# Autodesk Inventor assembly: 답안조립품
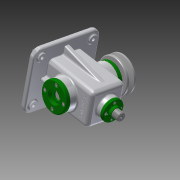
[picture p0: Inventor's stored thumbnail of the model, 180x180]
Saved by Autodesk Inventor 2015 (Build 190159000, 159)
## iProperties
Created: 2016-02
Part Number: 답안조립품
Document SubType Name: Assembly
Designer: Administrator
Author: Administrator
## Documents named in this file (19)
- C:\Users\Administrator\Desktop\답안조립품.iam
- C:\Users\Administrator\Desktop\본체.ipt
- C:\Users\Administrator\Desktop\460219V1005\V-벨트풀리.ipt
- C:\Users\Administrator\Desktop\460219V1005\고정핀.ipt
- C:\Users\Administrator\Desktop\460219V1005\뒤커버.ipt
- C:\Users\Administrator\Desktop\460219V1005\링크.ipt
- C:\Users\Administrator\Desktop\460219V1005\멈춤링 6 x 5.ipt
- C:\Users\Administrator\Desktop\460219V1005\멈춤링 15 x 1.ipt
- C:\Users\Administrator\Desktop\460219V1005\베어링 15 x 35 x 11.ipt
- C:\Users\Administrator\Desktop\460219V1005\볼트 M3 x 8.ipt
- C:\Users\Administrator\Desktop\460219V1005\볼트 M4 x 10.ipt
- C:\Users\Administrator\Desktop\460219V1005\상부부시.ipt
- C:\Users\Administrator\Desktop\460219V1005\슬라이드바.ipt
- C:\Users\Administrator\Desktop\460219V1005\앞커버.ipt
- C:\Users\Administrator\Desktop\460219V1005\오일실 15 25 7.ipt
- C:\Users\Administrator\Desktop\460219V1005\키 5 x 5 x 14.ipt
- C:\Users\Administrator\Desktop\460219V1005\편심축.ipt
- C:\Users\Administrator\Desktop\460219V1005\볼트 M6 x 12.ipt
- C:\Users\Administrator\Desktop\460219V1005\와셔.ipt
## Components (15 placed, 5 different names)
1. V-벨트풀리:1
2. 고정핀:1
3. ISO 4018 M6 x 12:1
4. ISO 4762 M4 x 10:1
5. ISO 4762 M4 x 10:2
6. ISO 4762 M4 x 10:3
7. ISO 4762 M4 x 10:4
8. ISO 4762 M3 x 8:2
9. ISO 4762 M3 x 8:3
10. ISO 4762 M3 x 8:4
11. ISO 4762 M3 x 8:5
12. ISO 4762 M4 x 10:5
13. ISO 4762 M4 x 10:6
14. ISO 4762 M4 x 10:7
15. ISO 4762 M4 x 10:8
